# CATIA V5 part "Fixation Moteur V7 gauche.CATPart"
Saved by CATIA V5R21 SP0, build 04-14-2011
Part number: MOTEURGAUCHE
Bounding box of the stored display mesh (mm): x -4.2 to 4.2, y -40 to 0, z -20 to 40
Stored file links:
  C:\Users\2027.DESARCY-LEMIE30\Desktop\Assemblage26.05\Fixation Moteur V7 gauche.CATPart
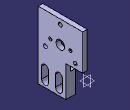
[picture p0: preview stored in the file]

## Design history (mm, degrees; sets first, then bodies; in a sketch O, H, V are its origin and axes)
Body1 (main body)
  Sketch1 on yz-plane, origin (0, 0, 0), H (0, 1, 0), V (0, 0, 1)
    line L1 (-40, 40) -> (0, 40)
    line L2 (0, 40) -> (0, 0)
    line L3 (0, 0) -> (-40, 0)
    line L4 (-40, 0) -> (-40, 40)
    point P3 (0, 0)
    length L4 = 40
    length L1 = 40
    horizontal: L1 H, L3 H
    vertical: L2 V, L4 V
    coincidence: P3 O
  Pad1: profile Sketch1, direction (1, 0, 0), length 4.2
  Sketch2 on end face of Pad1, origin (4.2, 0, 0), H (0, 1, 0), V (0, 0, 1)
    point P1 (-40, 0)
    line L1 (-40, 0) -> (-15, 0)
    line L2 (-15, 0) -> (-15, -20)
    line L3 (-15, -20) -> (-40, -20)
    line L4 (-40, -20) -> (-40, 0)
    reference projected point E1 (-40, 0) from vertex [face of Pad1 from Sketch1.L3 | end face of Pad1 | face of Pad1 from Sketch1.L4]
    length L2 = 20
    length L3 = 25
    horizontal: L1 H, L3 H
    vertical: L2 V, L4 V
    coincidence: P1 E1
  Pad2: profile Sketch2, direction (-1, 0, 0), length 8.4
  Sketch3 on end face of Pad2, origin (-4.2, 0, 0), H (0, -1, 0), V (0, 0, 1)
    point P1 (18.15, -5)
    line L1 (24.35, -5) -> (24.35, -15)
    line L2 (18.15, -15) -> (18.15, -5)
    point P2 (24.35, -5)
    point P3 (24.35, -15)
    point P4 (18.15, -15)
    axis line L3 (27.5, 2.3624) -> (27.5, -21.6714)
    reference projected line E1 (40, 0) -> (40, -20) from edge [end face of Pad2 | face of Pad2 from Sketch2.L4]
    arc A1 centre (21.25, -5) radius 3.1 from (24.35, -5) to (18.15, -5) ccw
    point P8 (10.7649, -15.4491)
    arc A2 centre (21.25, -15) radius 3.1 from (18.15, -15) to (24.35, -15) ccw
    point P9 (21.25, -15)
    point P10 (18.15, -15)
    point P11 (24.35, -15)
    point P12 (36.85, -5)
    point P13 (36.85, -15)
    line L4 (36.85, -15) -> (36.85, -5)
    point P14 (30.65, -5)
    arc A3 centre (33.75, -5) radius 3.1 from (30.65, -5) to (36.85, -5) cw
    point P16 (30.65, -15)
    line L5 (30.65, -5) -> (30.65, -15)
    point P17 (30.65, -15)
    point P18 (36.85, -15)
    point P19 (33.75, -15)
    arc A4 centre (33.75, -15) radius 3.1 from (36.85, -15) to (30.65, -15) cw
    reference projected line E2 (40, -20) -> (15, -20) from edge [end face of Pad2 | face of Pad2 from Sketch2.L3]
    distance L3 E1 = 12.5
    radius A1 = 3.1
    distance P9 P19 = 12.5
    length L4 = 10
    distance A4 E2 = 1.9
    vertical: L1 V, L2 V, L3 V
    tangency: A1 L1, A1 L2, A2 L1, A2 L2
    coincidence: P4 A2, L1 P11, L2 P10, P3 P11, P4 P10, P13 P18, P16 P17
    symmetry: P1 P12 L3, P4 P13 L3, L2 L4 L3, P2 P14 L3, A1 A3 L3, P3 P16 L3, L1 L5 L3, P11 P17 L3, P10 P18 L3, A2 A4 L3
  Pocket1: profile Sketch3, direction (1, 0, 0), through (limit type 3)
  Sketch4 on start face of Pad1, origin (0, 0, 0), H (0, -1, 0), V (0, 0, 1)
    construction line L1 (0, 20) -> (40, 20)
    point P1 (0, 20)
    point P2 (40, 20)
    reference projected line E1 (0, 40) -> (40, 40) from edge [start face of Pad1 | face of Pad1 from Sketch1.L1]
    reference projected line E2 (0, 0) -> (0, 40) from edge [start face of Pad1 | face of Pad2]
    reference projected line E3 (40, 40) -> (40, 0) from edge [start face of Pad1 | face of Pad1 from Sketch1.L4]
    construction line L2 (20, 40) -> (20, 0)
    point P3 (20, 40)
    point P4 (20, 0)
    reference projected line E4 (0, 40) -> (40, 40) from edge [start face of Pad1 | face of Pad1 from Sketch1.L1]
    reference projected line E5 (40, 0) -> (0, 0) from edge [start face of Pad1 | face of Pad1 from Sketch1.L3]
    reference projected line E6 (40, 40) -> (40, 0) from edge [start face of Pad1 | face of Pad1 from Sketch1.L4]
    circle A1 centre (20, 20) radius 4
    point P5 (20, 20)
    construction line L3 (20, 20) -> (0, 8.453)
    point P6 (0, 8.453)
    axis line L4 (20, 20) -> (40, 8.453)
    point P7 (40, 8.453)
    reference projected line E7 (40, 40) -> (40, 0) from edge [start face of Pad1 | face of Pad1 from Sketch1.L4]
    circle A2 centre (20, 35.5885) radius 1.75
    point P8 (20, 35.5885)
    point P9 (33.5, 12.2058)
    circle A3 centre (33.5, 12.2058) radius 1.75
    point P10 (6.5, 12.2058)
    circle A4 centre (6.5, 12.2058) radius 1.75
    distance E1 L1 = 20
    distance L2 E6 = 20
    radius A1 = 4
    angle L3 L2 = 120
    angle L2 L4 = 120
    radius A2 = 1.75
    distance P9 P10 = 27
    horizontal: L1 H
    coincidence: P1 E2, P2 E3, E4 P3, P4 E5, P5 L2, P6 V, P7 E7, P8 L2
    vertical: L2 V
    midpoint: P5 L2
    symmetry: A2 A3 L3, A3 A4 L2
  Pocket2: profile Sketch4, direction (1, 0, 0), through (limit type 3)
  Sketch5 on start face of Pad1, origin (0, -33.6663, 26.8229), H (0, 1, 0), V (0, 0, -1)
    point P1 (22.6663, 6.8229)
    axis line L1 (13.6663, 6.8229) -> (56.6573, 6.8229)
    point P2 (13.6663, 6.8229)
    reference projected circle E1 centre (13.6663, 6.8229) radius 4 from edge [start face of Pad1 | face of Pocket2 from Sketch4.A1]
    distance P2 P1 = 9
    horizontal: L1 H
    concentricity: P2 E1
    coincidence: P1 L1
  Hole1: placed by Sketch5, at (0, -11, 20) direction (1, 0, 0), diameter 3, through (limit type 6), counterbore diameter 6, counterbore depth 3
  RectPattern1: of Hole1, direction 1 instances 2, spacing 18, along face of Pad1 from Sketch1.L1 reversed
  Sketch6 on start face of Pad1, origin (0, 0, 0), H (0, -1, 0), V (0, 0, 1)
    line L1 (0, 0) -> (15, 0)
    line L2 (15, 0) -> (15, 8)
    line L3 (15, 8) -> (0, 8)
    line L4 (0, 8) -> (0, 0)
    reference projected line E1 (15, -20) -> (15, 0) from edge [end face of Pad2 | face of Pad2 from Sketch2.L2]
    length L2 = 8
    horizontal: L1 H, L3 H
    vertical: L2 V, L4 V
    coincidence: L2 E1
  Pocket3: profile Sketch6, direction (1, 0, 0), through (limit type 3)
